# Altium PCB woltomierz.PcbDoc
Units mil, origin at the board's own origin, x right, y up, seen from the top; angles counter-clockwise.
Board outline 6000 x 4000 mil, 2 copper layers (Top Layer, Bottom Layer); 24 components, 16 nets, 85 pads, 5 vias.
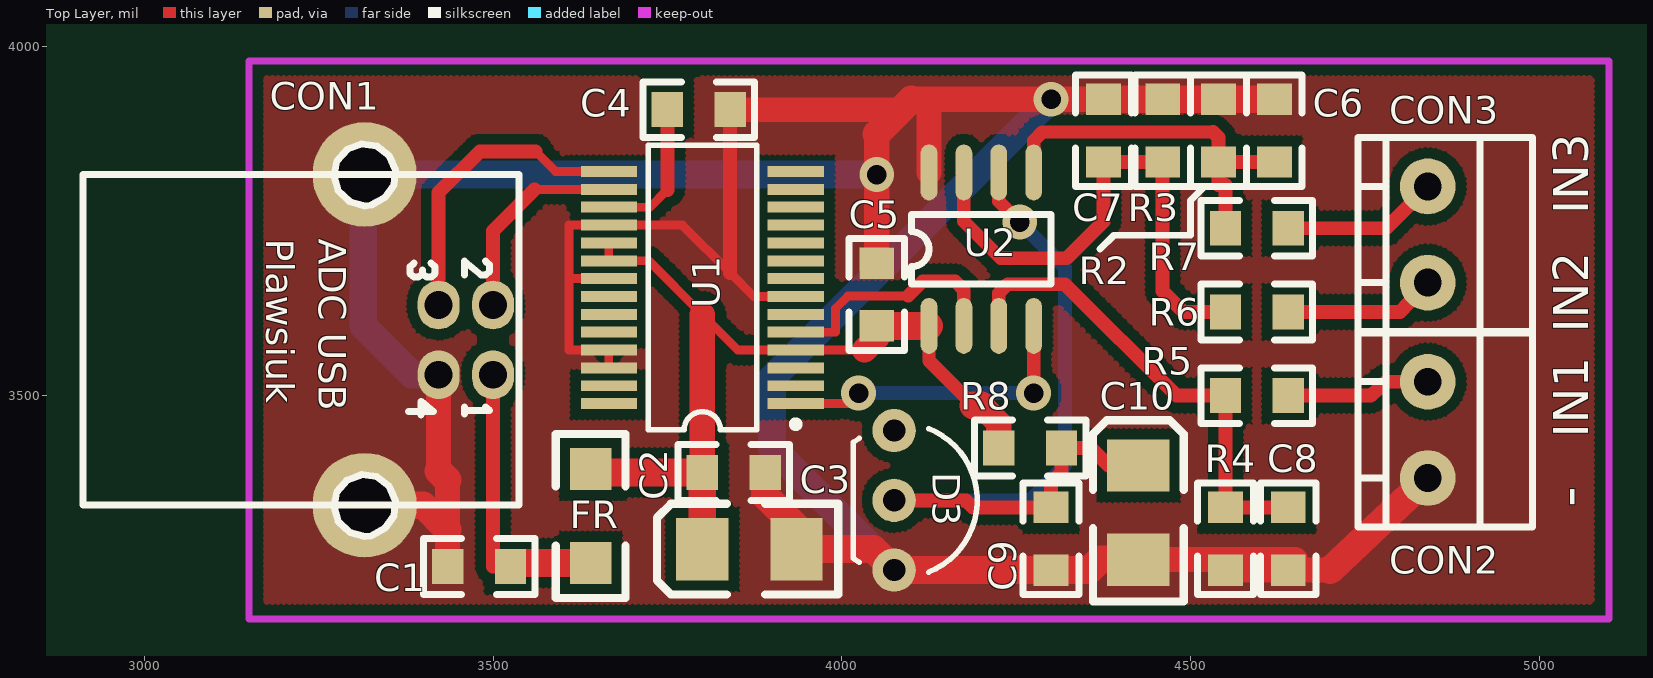
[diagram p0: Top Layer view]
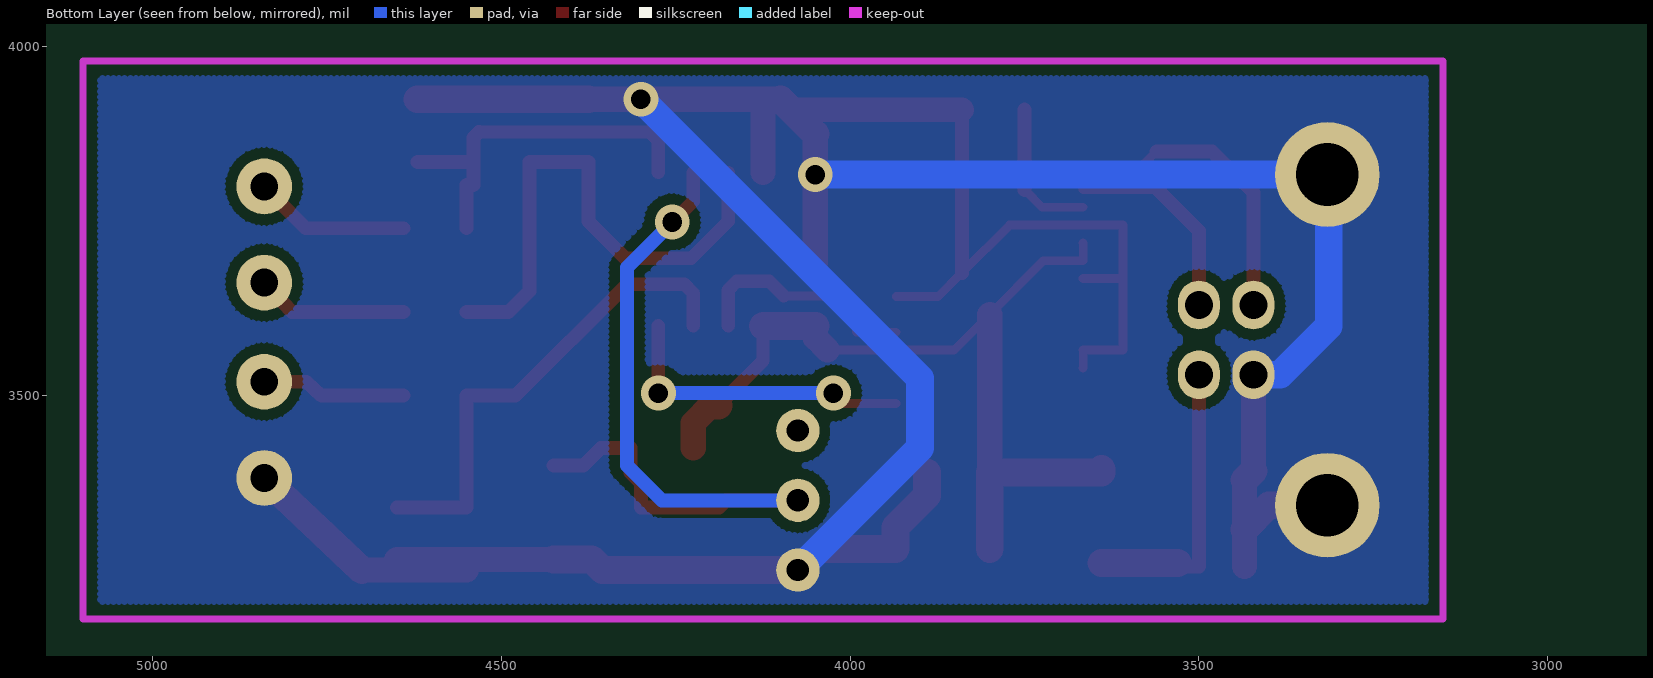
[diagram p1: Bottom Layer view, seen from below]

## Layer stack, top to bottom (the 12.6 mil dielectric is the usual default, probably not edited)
Top Layer: signal copper 1.4
Dielectric: dielectric 12.6, FR-4, Dk 4.8
Bottom Layer: signal copper 1.4

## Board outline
1000,1000 7000,1000 7000,5000 1000,5000

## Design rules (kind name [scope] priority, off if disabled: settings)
Clearance [All] p1: gap=15
ComponentClearance [All] p1: gap=10 collisioncheckmode=3 verticalgap=10
PolygonConnect [All] p1: connectstyle=Direct reliefconductorwidth=10 reliefentries=4 polygonreliefangle="90 Angle"
RoutingVias [All] p1: holewidth=28 width=50 viastyle="Through Hole" minholewidth=28 minwidth=50 maxholewidth=28 maxwidth=50
SMDNeckDown [All] p1: percent=80.000
SolderMaskExpansion [All] p1: expansion=4
TestPointUsage [All] p1: valid=0 allowmultiple=FALSE
Testpoint [All] p1: side=15 testpointundercomponent=TRUE minsize=40 maxsize=100 preferedsize=60 minholesize=0 maxholesize=40 preferedholesize=32 testpointgrid=1 style=1023 order=0123456789
Width Width_1 [innet('GND') or innet('VCC')] p1: maxlimit=40 minlimit=30 preferedwidth=40
Width [All] p2: maxlimit=20 minlimit=12 preferedwidth=20
17 further rules are at their usual default settings.

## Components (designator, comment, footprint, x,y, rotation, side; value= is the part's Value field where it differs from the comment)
C1 "10n" 0805 3525,3255 r180 top
C2 "100n" 0805 3800,3390 r0 top
C3 "10u" 3528 3800,3280 r180 top
C4 "100n" 0805 3750,3910 r0 top
C5 "100n" 0805 4050,3600 r90 top
C6 "100n" 0805 4620,3925 r270 top
C7 "100n" 0805 4375,3925 r270 top
C8 "100n" 0805 4640,3250 r90 top
C9 "100n" 0805 4300,3250 r90 top
C10 "10u" 3528 4425,3400 r90 top
CON1 "USB-B" USB-B 3500,3530 r270 top
CON2 "" CON2-3,5 4840,3520 r270 top
CON3 "" CON2-3,5 4840,3800 r270 top
D3 "LM385-2,5" LM385 4075,3350 r180 top
FR "4,7K" 1206 3640,3260 r90 top
R2 "100k" 0805 4540,3925 r270 top
R3 "100k" 0805 4460,3925 r270 top
R4 "100k" 0805 4550,3250 r90 top
R5 "2,2k" 0805 4640,3500 r180 top
R6 "2,2k" 0805 4640,3620 r180 top
R7 "2,2k" 0805 4640,3740 r180 top
R8 "1k" 0805 4225,3425 r0 top
U1 "FT232R" SSOP-28 3800,3655 r90 top
U2 "PIC12F683" so-8 4125,3600 r90 top (schematic designator US1)

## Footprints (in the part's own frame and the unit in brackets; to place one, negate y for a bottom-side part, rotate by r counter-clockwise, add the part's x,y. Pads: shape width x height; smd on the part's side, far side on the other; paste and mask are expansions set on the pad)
0805 [mil]
  rect 45x50 smd: 1(0,0) 2(90,0)
  silkscreen extent -35,-40 125,40
1206 [mil]
  rect 60x60 smd: 1(0,0) 2(135,0)
  silkscreen extent -50,-50 185,50
3528 [mil]
  rect 75x90 smd: 1(0,0) 2(-135,0)
  silkscreen extent -195,-65 65,65
CON2-3,5 [mil]
  round 80 hole 40: 1(0,0) 2(138,0)
  silkscreen extent -70,-100 208,150
LM385 [mil]
  round 62 hole 32: 1(0,100) 2(0,0) 3(0,-100)
  silkscreen extent -119,-103 58,103
so-8 [mil]
  oval 80x24 smd: 1(0,0) 2(0,-50) 3(0,-100) 4(0,-150) 5(220,-150) 6(220,-100) 7(220,-50) 8(220,0)
  silkscreen extent 60,-175 160,25
SSOP-28 [mm] "SSOP, Plastic; 28 Leads; Body Width 5.3 mm; Pitch 0.65 mm"
  rect 0.4x2.05 smd: 1(-4.225,-3.4) 2(-3.575,-3.4) 3(-2.925,-3.4) 4(-2.275,-3.4) 5(-1.625,-3.4) 6(-0.975,-3.4) 7(-0.325,-3.4) 8(0.325,-3.4) 9(0.975,-3.4) 10(1.625,-3.4) 11(2.275,-3.4) 12(2.925,-3.4) 13(3.575,-3.4) 14(4.225,-3.4) 15(4.225,3.4) 16(3.575,3.4) 17(2.925,3.4) 18(2.275,3.4) 19(1.625,3.4) 20(0.975,3.4) 21(0.325,3.4) 22(-0.325,3.4) 23(-0.975,3.4) 24(-1.625,3.4) 25(-2.275,3.4) 26(-2.925,3.4) 27(-3.575,3.4) 28(-4.225,3.4)
  silkscreen extent -5.18,-3.52 5.17,1.98
USB-B [mil]
  oval 70x60 hole 40: 1(0,0) 2(-100,0) 3(-100,-78) 4(0,-78)
  round 150 hole 90: 5(-287,-184) 6(187,-184)
  Bottom Layer lines w10: -285,-186 -287,-184 -290,-181
  silkscreen extent -331,-588 232,37

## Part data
C1 C2 C4 C5 C6 C7 C8 C9: library part Cap, "Capacitor"
C3: library part "Cap Pol1", "Polarized Capacitor (Radial)"
C10: library part ELECTRO2, "Electrolytic Capacitor"
CON2 CON3: library part CON2, "Connector"
D3: library part ZENER1, "Zener Diode"
FR R4 R5 R6 R7 R8: library part Res2, "Resistor"
R2 R3: library part RES2
U2: library part PIC12F629

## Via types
v1: diameter 50, hole 28, Top Layer to Bottom Layer, 5 vias

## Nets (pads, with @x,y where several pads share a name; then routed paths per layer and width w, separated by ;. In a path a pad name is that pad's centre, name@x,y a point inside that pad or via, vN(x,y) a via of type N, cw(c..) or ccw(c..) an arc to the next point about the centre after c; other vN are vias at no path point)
AN1: C8.2 R4.2 R5.2 U2.3 | length 703.4
  Top Layer w19.2: U2.3 4225,3647.1 4237.5,3659.6 4320,3659.6
  Top Layer w20: 4320,3659.6 4479.6,3500 R5.2 R4.2 C8.2@4650,3340
AN2: C7.2 R3.2 R6.2 U2.7 | length 771.3
  Top Layer w19.2: U2.7 4175,3750 4228,3697
  Top Layer w20: 4228,3697 4322,3697 4375,3750 C7.2 R3.2 4460,3650 4490,3620 R6.2
AN3: C6.2 R2.2 R7.2 U2.5 | length 539
  Top Layer w19.2: U2.5 4275,3865.5 4287.5,3878 4532,3878
  Top Layer w20: 4532,3878 4540,3870 R2.2 ; R7.2 4550,3802 4540,3802 R2.2 ; C6.2 R2.2
GND: C1.2 C2.2 C3.2 C4.2 C5.2 C6.1 C7.1 C8.1 C9.1 C10.2 CON1.4 CON1.5 CON1.6 CON2.2 D3.1 R2.1 R3.1 R4.1 U1.7 U1.18 U1.21 U1.25 U1.26 U2.8 | length 5673.7
  Top Layer w12.6: U1.26 3666,3539.84 3666,3565.43 3609,3565.43 3609,3667.8 ; U1.21 3609,3667.8 ; U1.7 3873.8,3642.2 3840,3676 3771.43,3744.57 U1.18 3609,3744.57 3609,3667.8
  Top Layer w20: 3840,3676 C4.2
  Top Layer w35: C4.2 4080,3910
  Top Layer w36: 3422,3392 CON1.4 ; C1.2 3435,3308 3435,3379 ; C5.2 v1(4050,3817) 4050,3875 ; 4100,3925 4125,3925 ; U2.8 4125,3892 4125,3925 ; C7.1 v1(4300,3925) 4158,3925 4125,3925 ; C10.2 4550,3265 4650,3265 C8.1@4650,3250 ; R4.1 C8.1@4650,3250 ; 4700,3250 C8.1@4650,3250
  Top Layer w40: CON1.6 3400,3343 3435,3308 ; 3422,3392 3435,3379 ; C2.2 3890,3357 3935,3312 C3.2 4045,3280 D3.1 C9.1 4355,3250 4370,3265 C10.2 ; 4050,3875 4100,3925 ; C7.1 R3.1 R2.1 C6.1 ; 4700,3250 CON2.2
  Bottom Layer w40: CON1.5@3314,3815 3314,3600 3384,3530 CON1.4 ; CON1.5 v1(4050,3817) ; D3.1 3900,3425 3900,3525 v1(4300,3925)
NetC1_1: C1.1 CON1.1 FR.1 | length 417.1
  Top Layer w20: CON1.1 3500,3255 C1.1 C1.1@3530,3260
  Top Layer w40: C1.1@3530,3260 FR.1
NetC4_1: C4.1 U1.17 | length 209.1
  Top Layer w12.6: U1.17 3725,3770.16 3750,3795.16
  Top Layer w20: 3750,3795.16 C4.1
NetC4_2:  | length 0.1
  Top Layer w12.6: 3666,3565.43 3666.14,3565.43
NetC9_2: C9.2 C10.1 D3.2 R8.2 U2.6 | length 1165.8
  Top Layer w19.2: U2.6 4225,3779 v1(4255,3749)
  Top Layer w20: D3.2 4178,3350 4188,3340 C9.2 4300,3375 4315,3390 R8.2 4357,3425 4382,3400 C10.1
  Bottom Layer w20: D3.2 4270,3350 4320,3400 4320,3684 v1(4255,3749)
NetCON1_2: CON1.2 U1.16 | length 296.9
  Top Layer w12.6: 3559.75,3795.75 U1.16
  Top Layer w20: CON1.2 3500,3736 3559.75,3795.75
NetCON1_3: CON1.3 U1.15 | length 441.5
  Top Layer w12.6: 3561,3850 3589.66,3821.34 U1.15
  Top Layer w20: CON1.3 3422,3791 3481,3850 3561,3850
NetCON2_1: CON2.1 R5.1 | length 207.7
  Top Layer w20: R5.1 4758,3500 4780,3520 CON2.1
NetCON3_1: CON3.1 R7.1 | length 224.9
  Top Layer w20: R7.1 4780,3740 CON3.1
NetCON3_2: CON3.2 R6.1 | length 218
  Top Layer w20: R6.1 4800,3620 CON3.2
RXD: U1.5 U2.2 | length 347.9
  Top Layer w12.6: U1.5 3991,3591.02 3991,3625 4009,3643 4095,3643
  Top Layer w19.2: 4095,3643 4116,3664 4162.5,3664 4175,3651.5 U2.2
TXD: U1.1 U2.4 | length 443.7
  Top Layer w12.6: U1.1 4009,3488.66 v1(4024,3503.66)
  Top Layer w19.2: v1(4275,3503.66) U2.4
  Bottom Layer w20: v1(4024,3503.66) v1(4275,3503.66)
VCC: C2.1 C3.1 C5.1 FR.2 R8.1 U1.4 U1.19 U1.20 U2.1 | length 1286.3
  Top Layer w12.6: U1.19 3666,3718.98 3666,3693.39 U1.20 3723,3693.39 3800,3616.39 3850.95,3565.43 U1.4 4032.43,3565.43
  Top Layer w19.2: U2.1 4125,3550 4189,3486
  Top Layer w36: C2.1 3800,3616.39 ; 4032.43,3565.43 4050,3583 C5.1 ; 4200,3486 4225,3461 R8.1
  Top Layer w40: FR.2 3640,3390 C2.1 C3.1 ; C5.1 U2.1 ; 4189,3486 4200,3486
pads on no net: D3.3 U1.2 U1.3 U1.6 U1.8 U1.9 U1.10 U1.11 U1.12 U1.13 U1.14 U1.22 U1.23 U1.24 U1.27 U1.28

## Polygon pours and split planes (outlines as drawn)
GND on Top Layer (hatched 90Degree grid 8 track 10, remove dead copper): 3140,4000 5120,4000 5120,3160 3120,3160 3120,4000
GND on Bottom Layer (hatched 90Degree grid 8 track 10, remove dead copper): 3125,4000 5125,4000 5125,3150 3125,3150

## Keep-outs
Keep-Out Layer:
  lines w10: 3150,3180 5100,3180 5100,3980 3150,3980 3150,3180

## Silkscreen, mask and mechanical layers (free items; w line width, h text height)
Top Overlay:
  lines w10: 4370,3710 4390,3730 4500,3730 4500,3780 4520,3800
  text "IN3" at 5070,3760 h50 r90
  text "Plawsiuk" at 3175,3725 h40 r270
  text "ADC USB" at 3250,3725 h40 r270
  text "IN2" at 5070,3590 h50 r90
  text "IN1" at 5070,3440 h50 r90
  text "-" at 5070,3340 h60 r90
